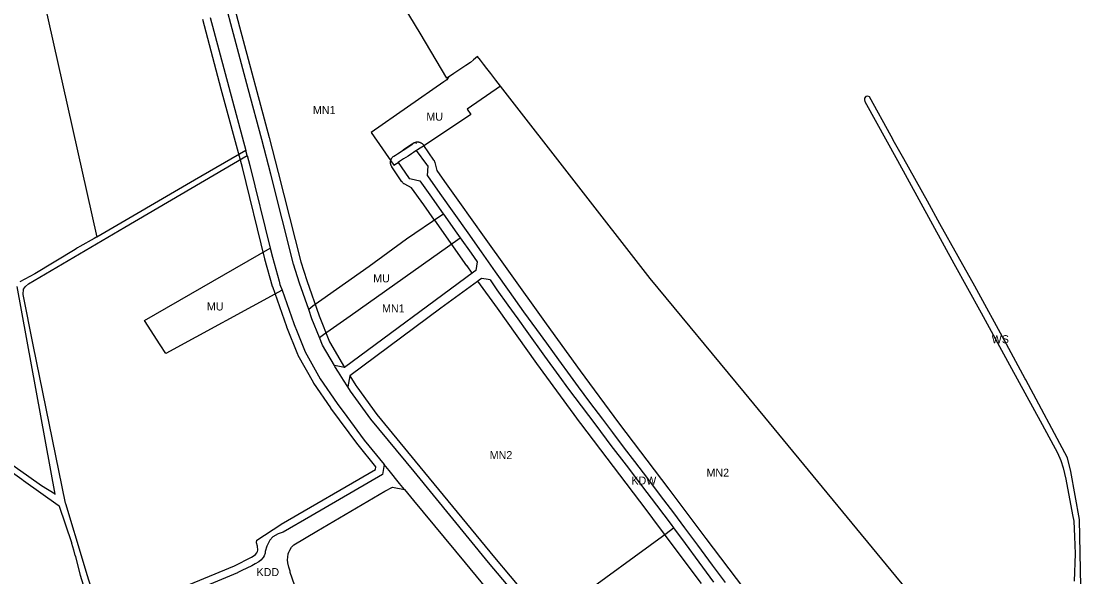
# Model space of a CAD drawing. Extents: x 7435758 to 7439981, y 5550649 to 5554049.
# Drawn here: x 7437107 to 7437796, y 5552004 to 5552365 of the extents above; entities that cross this region are included whole.
import ezdxf

# ---------------------------------------------------------------- set-up
doc = ezdxf.new("R2010")
doc.units = 0
for name, color, linetype in [('linie_rozgraniczające', 7, 'Continuous'), ('linie_zabudowy_nieprzekraczalne', 7, 'Continuous'), ('oznaczenia_przeznaczen', 7, 'Continuous')]:
    doc.layers.add(name, color=color, linetype=linetype)

msp = doc.modelspace()

# ---------------------------------------------------------------- linework, layer by layer
at = {"layer": 'linie_rozgraniczające'}
for p, q in [((7437079.69, 5552568.34), (7437156.51, 5552224.35)), ((7437366.62, 5552356.85), (7437322.07, 5552430.86)), ((7437244.46, 5552359.72), (7437240.84, 5552373.46)), ((7437230.33, 5552367.12), (7437242.26, 5552321.71)), ((7437254.97, 5552320.65), (7437244.46, 5552359.72)), ((7437384.15, 5552327.72), (7437366.62, 5552356.85)), ((7437399.4, 5552337.9), (7437396.39, 5552335.89)), ((7437401.44, 5552339.58), (7437399.4, 5552337.9)), ((7437404.02, 5552341.71), (7437401.44, 5552339.58)), ((7437405.85, 5552339.36), (7437404.02, 5552341.71)), ((7437407.81, 5552336.84), (7437405.85, 5552339.36)), ((7437396.39, 5552335.89), (7437388.59, 5552330.68)), ((7437410.14, 5552333.85), (7437407.81, 5552336.84)), ((7437412.64, 5552330.63), (7437410.14, 5552333.85)), ((7437382.18, 5552325.29), (7437334.96, 5552292.27)), ((7437384, 5552326.57), (7437382.18, 5552325.29)), ((7437385.04, 5552328.32), (7437384, 5552326.57)), ((7437385.04, 5552328.32), (7437384.15, 5552327.72)), ((7437388.59, 5552330.68), (7437385.04, 5552328.32)), ((7437415.98, 5552326.35), (7437412.64, 5552330.63)), ((7437418.98, 5552322.48), (7437415.98, 5552326.35)), ((7437242.26, 5552321.71), (7437253.38, 5552280.67)), ((7437263.81, 5552287.76), (7437254.97, 5552320.65)), ((7437418.98, 5552322.48), (7437397.35, 5552307.52)), ((7437516.1, 5552197.62), (7437418.98, 5552322.48)), ((7437655.54, 5552314.73), (7437655.41, 5552313.64)), ((7437655.41, 5552313.64), (7437655.82, 5552312.48)), ((7437656.32, 5552315.76), (7437655.54, 5552314.73)), ((7437655.82, 5552312.48), (7437676.89, 5552274.12)), ((7437657.66, 5552315.99), (7437656.32, 5552315.76)), ((7437658.85, 5552315.59), (7437657.66, 5552315.99)), ((7437672.77, 5552289.88), (7437658.85, 5552315.59)), ((7437399.69, 5552303.96), (7437369.51, 5552283.88)), ((7437397.35, 5552307.52), (7437399.69, 5552303.96)), ((7437334.96, 5552292.27), (7437349.56, 5552271.08)), ((7437675.01, 5552285.82), (7437672.77, 5552289.88)), ((7437269.61, 5552265.22), (7437263.81, 5552287.76)), ((7437369.44, 5552283.81), (7437365.01, 5552281.08)), ((7437369.51, 5552283.88), (7437369.44, 5552283.81)), ((7437681.11, 5552275.27), (7437675.01, 5552285.82)), ((7437174.82, 5552230.93), (7437254.27, 5552277.38)), ((7437253.34, 5552280.68), (7437220.13, 5552261.4)), ((7437253.38, 5552280.67), (7437253.34, 5552280.68)), ((7437254.27, 5552277.38), (7437253.38, 5552280.67)), ((7437254.27, 5552277.38), (7437256.04, 5552270.85)), ((7437358.84, 5552277.08), (7437355.98, 5552275.2)), ((7437360.99, 5552278.49), (7437358.84, 5552277.08)), ((7437362.29, 5552279.34), (7437360.99, 5552278.49)), ((7437362.39, 5552279.41), (7437362.29, 5552279.34)), ((7437363.85, 5552280.37), (7437362.39, 5552279.41)), ((7437364.34, 5552280.67), (7437363.85, 5552280.37)), ((7437363.85, 5552280.37), (7437363.85, 5552280.37)), ((7437365.01, 5552281.08), (7437364.34, 5552280.67)), ((7437371.06, 5552271.67), (7437364.34, 5552280.67)), ((7437256.04, 5552270.85), (7437269.23, 5552217.2)), ((7437349.56, 5552271.08), (7437351.43, 5552272.2)), ((7437351.43, 5552272.2), (7437352.43, 5552272.86)), ((7437352.45, 5552272.88), (7437352.43, 5552272.86)), ((7437352.43, 5552272.86), (7437359.11, 5552263.09)), ((7437353.35, 5552273.47), (7437352.45, 5552272.88)), ((7437355.98, 5552275.2), (7437353.35, 5552273.47)), ((7437371.79, 5552270.7), (7437371.06, 5552271.67)), ((7437371.52, 5552264.31), (7437371.81, 5552270.6)), ((7437371.82, 5552270.67), (7437371.79, 5552270.7)), ((7437371.81, 5552270.6), (7437371.82, 5552270.67)), ((7437676.89, 5552274.12), (7437713.49, 5552207.37)), ((7437696.41, 5552247.65), (7437681.11, 5552275.27)), ((7437284.35, 5552206.9), (7437269.61, 5552265.22)), ((7437359.11, 5552263.09), (7437359.48, 5552262.54)), ((7437359.48, 5552262.54), (7437360.8, 5552262.26)), ((7437360.8, 5552262.26), (7437366.56, 5552261.03)), ((7437371.66, 5552264.12), (7437371.52, 5552264.31)), ((7437379.76, 5552252.77), (7437371.66, 5552264.12)), ((7437220.13, 5552261.4), (7437156.51, 5552224.35)), ((7437366.56, 5552261.03), (7437373.02, 5552251.83)), ((7437373.02, 5552251.83), (7437381.76, 5552239.54)), ((7437388.85, 5552239.92), (7437379.76, 5552252.77)), ((7437704.46, 5552233.13), (7437696.41, 5552247.65)), ((7437380.2, 5552238.3), (7437357.78, 5552223.09)), ((7437380.21, 5552238.29), (7437380.2, 5552238.3)), ((7437381.85, 5552239.42), (7437380.21, 5552238.29)), ((7437381.76, 5552239.54), (7437381.85, 5552239.42)), ((7437381.85, 5552239.42), (7437390.59, 5552227.08)), ((7437397.86, 5552227.21), (7437388.85, 5552239.92)), ((7437112.18, 5552194.08), (7437174.82, 5552230.93)), ((7437716.46, 5552211.77), (7437704.46, 5552233.13)), ((7437154.93, 5552223.46), (7437145.61, 5552218.23)), ((7437156.01, 5552224.06), (7437154.93, 5552223.46)), ((7437156.51, 5552224.35), (7437156.01, 5552224.06)), ((7437321.15, 5552173.29), (7437391.19, 5552222.77)), ((7437357.78, 5552223.09), (7437333.62, 5552205.36)), ((7437390.59, 5552227.08), (7437392.81, 5552223.94)), ((7437391.18, 5552222.78), (7437392.81, 5552223.94)), ((7437391.19, 5552222.77), (7437391.18, 5552222.78)), ((7437392.81, 5552223.94), (7437399.86, 5552213.99)), ((7437406.64, 5552214.78), (7437397.86, 5552227.21)), ((7437142.42, 5552216.41), (7437116.22, 5552200.66)), ((7437143.39, 5552216.99), (7437142.42, 5552216.41)), ((7437144.04, 5552217.35), (7437143.39, 5552216.99)), ((7437145.61, 5552218.23), (7437144.04, 5552217.35)), ((7437187.49, 5552170.33), (7437269.23, 5552217.2)), ((7437269.23, 5552217.2), (7437270.66, 5552211.39)), ((7437399.86, 5552213.99), (7437403.84, 5552208.39)), ((7437415.77, 5552201.94), (7437406.64, 5552214.78)), ((7437270.66, 5552211.39), (7437275.01, 5552195.81)), ((7437288.27, 5552194.53), (7437284.35, 5552206.9)), ((7437403.84, 5552208.39), (7437403.39, 5552205.59)), ((7437713.49, 5552207.37), (7437731.24, 5552175.15)), ((7437727.15, 5552192.6), (7437716.46, 5552211.77)), ((7437116.22, 5552200.66), (7437106.53, 5552195.37)), ((7437333.62, 5552205.36), (7437297.06, 5552179.5)), ((7437401.33, 5552201.61), (7437317.61, 5552139.76)), ((7437402.94, 5552202.79), (7437401.33, 5552201.61)), ((7437403.39, 5552205.59), (7437402.94, 5552202.79)), ((7437424.78, 5552189.16), (7437415.77, 5552201.94)), ((7437110.17, 5552192.24), (7437112.18, 5552194.08)), ((7437275.01, 5552195.81), (7437275.61, 5552193.69)), ((7437275.61, 5552193.69), (7437276.92, 5552189.99)), ((7437294.3, 5552177.32), (7437288.27, 5552194.53)), ((7437403.96, 5552195.62), (7437380.16, 5552178.26)), ((7437405.11, 5552196.45), (7437403.96, 5552195.62)), ((7437406.64, 5552197.56), (7437405.11, 5552196.45)), ((7437409.57, 5552197.05), (7437406.64, 5552197.56)), ((7437412.16, 5552196.6), (7437409.57, 5552197.05)), ((7437412.16, 5552196.6), (7437416.63, 5552190.24)), ((7437577.43, 5552123.38), (7437516.1, 5552197.62)), ((7437104.48, 5552192.3), (7437129.36, 5552057.48)), ((7437108.62, 5552187.06), (7437108.96, 5552190.6)), ((7437115.07, 5552154.38), (7437108.62, 5552187.06)), ((7437108.96, 5552190.6), (7437110.17, 5552192.24)), ((7437276.92, 5552189.99), (7437201.36, 5552148.79)), ((7437276.92, 5552189.99), (7437284.61, 5552168.24)), ((7437416.63, 5552190.24), (7437423.78, 5552180.21)), ((7437434.2, 5552175.93), (7437424.78, 5552189.16)), ((7437747.82, 5552154.95), (7437727.15, 5552192.6)), ((7437297.06, 5552179.5), (7437294.3, 5552177.32)), ((7437423.78, 5552180.21), (7437430.1, 5552171.36)), ((7437296.36, 5552171.43), (7437294.3, 5552177.32)), ((7437303.97, 5552161.15), (7437321.15, 5552173.29)), ((7437380.16, 5552178.26), (7437320.93, 5552134.39)), ((7437442.45, 5552164.48), (7437434.2, 5552175.93)), ((7437731.24, 5552175.15), (7437749.69, 5552141.43)), ((7437197.73, 5552154.43), (7437187.49, 5552170.33)), ((7437284.61, 5552168.24), (7437284.8, 5552167.7)), ((7437284.8, 5552167.7), (7437286.68, 5552162.96)), ((7437301.2, 5552159.28), (7437296.36, 5552171.43)), ((7437430.1, 5552171.36), (7437436.07, 5552163.04)), ((7437286.68, 5552162.96), (7437291.87, 5552149.93)), ((7437301.2, 5552159.28), (7437303.97, 5552161.15)), ((7437303.25, 5552154.13), (7437301.2, 5552159.28)), ((7437436.07, 5552163.04), (7437447.53, 5552147.14)), ((7437448.98, 5552155.5), (7437442.45, 5552164.48)), ((7437136.22, 5552051.57), (7437115.07, 5552154.38)), ((7437201.36, 5552148.79), (7437197.73, 5552154.43)), ((7437310.95, 5552141.04), (7437303.25, 5552154.13)), ((7437456.77, 5552144.64), (7437448.98, 5552155.5)), ((7437760, 5552132.4), (7437747.82, 5552154.95)), ((7437291.87, 5552149.93), (7437301.69, 5552132.42)), ((7437447.53, 5552147.14), (7437456.84, 5552134.23)), ((7437311.29, 5552140.46), (7437310.95, 5552141.04)), ((7437317.61, 5552139.76), (7437310.95, 5552141.04)), ((7437313.58, 5552136.79), (7437311.29, 5552140.46)), ((7437464.33, 5552134.2), (7437456.77, 5552144.64)), ((7437749.69, 5552141.43), (7437770.97, 5552102.66)), ((7437301.69, 5552132.42), (7437312.76, 5552116.27)), ((7437316.93, 5552131.42), (7437313.58, 5552136.79)), ((7437319.6, 5552127.13), (7437316.93, 5552131.42)), ((7437320.93, 5552134.39), (7437319.6, 5552127.13)), ((7437456.84, 5552134.23), (7437463.18, 5552125.67)), ((7437469.54, 5552127.2), (7437464.33, 5552134.2)), ((7437760.4, 5552131.68), (7437760, 5552132.4)), ((7437787.5, 5552080.98), (7437760.4, 5552131.68)), ((7437321.38, 5552124.27), (7437319.6, 5552127.13)), ((7437334.65, 5552106.1), (7437321.38, 5552124.27)), ((7437463.18, 5552125.67), (7437471.29, 5552114.9)), ((7437477.04, 5552117.26), (7437469.54, 5552127.2)), ((7437712.83, 5551959.48), (7437577.43, 5552123.38)), ((7437312.76, 5552116.27), (7437318.98, 5552107.87)), ((7437471.29, 5552114.9), (7437480.87, 5552102.18)), ((7437485.41, 5552106.1), (7437477.04, 5552117.26)), ((7437318.98, 5552107.87), (7437330.32, 5552092.58)), ((7437362.72, 5552072.08), (7437334.65, 5552106.1)), ((7437491.86, 5552097.54), (7437485.41, 5552106.1)), ((7437480.87, 5552102.18), (7437490.64, 5552089.14)), ((7437499.63, 5552087.22), (7437491.86, 5552097.54)), ((7437770.97, 5552102.66), (7437781.02, 5552084.36)), ((7437330.32, 5552092.58), (7437343.33, 5552076.64)), ((7437490.64, 5552089.14), (7437500.52, 5552076.22)), ((7437506.29, 5552078.56), (7437499.63, 5552087.22)), ((7437781.02, 5552084.36), (7437783.21, 5552079.3)), ((7437087.82, 5552081.28), (7437107.84, 5552067.1)), ((7437112.44, 5552068.75), (7437099.88, 5552077.62)), ((7437343.33, 5552076.64), (7437342.16, 5552070.19)), ((7437346.52, 5552072.73), (7437343.33, 5552076.64)), ((7437500.52, 5552076.22), (7437510.48, 5552063.12)), ((7437514.63, 5552067.55), (7437506.29, 5552078.56)), ((7437783.21, 5552079.3), (7437784.67, 5552074.52)), ((7437789.65, 5552072.11), (7437787.5, 5552080.98)), ((7437342.16, 5552070.19), (7437295.7, 5552043.19)), ((7437353.33, 5552064.39), (7437346.52, 5552072.73)), ((7437411.17, 5552013.03), (7437362.72, 5552072.08)), ((7437784.67, 5552074.52), (7437786.41, 5552067.27)), ((7437795.23, 5552040.98), (7437789.65, 5552072.11)), ((7437107.84, 5552067.1), (7437108.81, 5552066.42)), ((7437108.81, 5552066.42), (7437131.4, 5552050.38)), ((7437120.68, 5552062.91), (7437112.44, 5552068.75)), ((7437129.38, 5552057.35), (7437120.68, 5552062.91)), ((7437356.55, 5552060.45), (7437353.33, 5552064.39)), ((7437510.48, 5552063.12), (7437520.24, 5552050.34)), ((7437522.95, 5552056.67), (7437514.63, 5552067.55)), ((7437786.41, 5552067.27), (7437790.79, 5552044.05)), ((7437129.36, 5552057.48), (7437129.38, 5552057.35)), ((7437299.49, 5552033.33), (7437343.69, 5552059.39)), ((7437343.69, 5552059.39), (7437348.84, 5552062.06)), ((7437348.84, 5552062.06), (7437356.55, 5552060.45)), ((7437356.55, 5552060.45), (7437362.34, 5552053.36)), ((7437531.55, 5552045.38), (7437522.95, 5552056.67)), ((7437131.4, 5552050.38), (7437132.1, 5552049.91)), ((7437132.1, 5552049.91), (7437132.17, 5552049.71)), ((7437132.17, 5552049.71), (7437140.08, 5552026.01)), ((7437136.35, 5552051.15), (7437136.22, 5552051.57)), ((7437147.89, 5552013.16), (7437136.35, 5552051.15)), ((7437362.34, 5552053.36), (7437395.89, 5552012.73)), ((7437520.24, 5552050.34), (7437529.75, 5552037.72)), ((7437295.7, 5552043.19), (7437277.58, 5552032.65)), ((7437538.83, 5552035.57), (7437531.55, 5552045.38)), ((7437790.79, 5552044.05), (7437791.58, 5552039.97)), ((7437526.54, 5552031.99), (7437531.36, 5552035.54)), ((7437529.75, 5552037.72), (7437531.36, 5552035.54)), ((7437531.36, 5552035.54), (7437538.85, 5552025.41)), ((7437547.22, 5552024.23), (7437538.83, 5552035.57)), ((7437791.58, 5552039.97), (7437791.99, 5552029.95)), ((7437796.11, 5551997.41), (7437795.23, 5552040.98)), ((7437270.9, 5552029.62), (7437268.91, 5552027.62)), ((7437274.5, 5552031.78), (7437270.9, 5552029.62)), ((7437276.3, 5552032.26), (7437274.5, 5552031.78)), ((7437277.58, 5552032.65), (7437276.3, 5552032.26)), ((7437284.61, 5552024.56), (7437299.49, 5552033.33)), ((7437465.45, 5551987.36), (7437526.53, 5552031.99)), ((7437526.53, 5552031.99), (7437526.54, 5552031.99)), ((7437791.99, 5552029.95), (7437792.45, 5552018.67)), ((7437140.08, 5552026.01), (7437140.19, 5552025.68)), ((7437140.19, 5552025.68), (7437141.37, 5552021.3)), ((7437141.37, 5552021.3), (7437142.34, 5552017.69)), ((7437267.07, 5552023.68), (7437266.07, 5552020.21)), ((7437268.91, 5552027.62), (7437267.07, 5552023.68)), ((7437281.43, 5552019.86), (7437282.01, 5552021.07)), ((7437282.01, 5552021.07), (7437283.12, 5552023.01)), ((7437283.12, 5552023.01), (7437284.61, 5552024.56)), ((7437538.85, 5552025.41), (7437547.91, 5552013.21)), ((7437551.91, 5552017.91), (7437547.22, 5552024.23)), ((7437142.34, 5552017.69), (7437142.38, 5552017.52)), ((7437142.38, 5552017.52), (7437145.78, 5552004.91)), ((7437263.22, 5552014.62), (7437261.76, 5552013.45)), ((7437264.65, 5552016.34), (7437263.22, 5552014.62)), ((7437265.32, 5552017.31), (7437264.65, 5552016.34)), ((7437266.04, 5552019.16), (7437265.32, 5552017.31)), ((7437266.07, 5552020.21), (7437266.04, 5552019.16)), ((7437280.53, 5552014.69), (7437280.61, 5552016.59)), ((7437280.69, 5552012.8), (7437280.53, 5552014.69)), ((7437280.61, 5552016.59), (7437280.93, 5552018.66)), ((7437280.93, 5552018.66), (7437281.43, 5552019.86)), ((7437556.73, 5552011.36), (7437551.91, 5552017.91)), ((7437792.45, 5552018.67), (7437791.72, 5552000.89)), ((7437150.34, 5552005.1), (7437147.89, 5552013.16)), ((7437250.76, 5552007.86), (7437248.29, 5552006.53)), ((7437257.28, 5552010.98), (7437250.76, 5552007.86)), ((7437259.45, 5552012.09), (7437257.28, 5552010.98)), ((7437261.76, 5552013.45), (7437259.45, 5552012.09)), ((7437281.35, 5552010.13), (7437280.69, 5552012.8)), ((7437282.18, 5552007.32), (7437281.35, 5552010.13)), ((7437282.21, 5552006.54), (7437282.18, 5552007.32)), ((7437395.89, 5552012.73), (7437419.08, 5551984.95)), ((7437438.35, 5551980.83), (7437411.17, 5552013.03)), ((7437547.91, 5552013.21), (7437557.39, 5552000.34)), ((7437565.08, 5552000.1), (7437556.73, 5552011.36)), ((7437145.78, 5552004.91), (7437151.85, 5551984.9)), ((7437152.86, 5551996.81), (7437150.34, 5552005.1)), ((7437247.92, 5552006.38), (7437206.29, 5551989.07)), ((7437248.29, 5552006.53), (7437247.92, 5552006.38)), ((7437288.06, 5551989.83), (7437282.21, 5552006.54))]:
    msp.add_line(p, q, dxfattribs=at)
at = {"layer": 'linie_zabudowy_nieprzekraczalne'}
for points in [[(7437120.71, 5552853.45), (7437125.86, 5552836.94), (7437125.94, 5552836.66), (7437131.09, 5552815.87), (7437153.26, 5552730.42), (7437165.89, 5552683.76), (7437165.92, 5552683.63), (7437165.93, 5552683.61), (7437177.48, 5552635.16), (7437206.88, 5552523.96), (7437206.89, 5552523.93), (7437225.25, 5552452.28), (7437249.29, 5552361.01), (7437268.64, 5552289.06), (7437268.66, 5552289.01), (7437274.45, 5552266.46), (7437274.46, 5552266.44), (7437289.16, 5552208.27), (7437293.01, 5552196.12), (7437301.05, 5552173.18), (7437307.75, 5552156.34), (7437317.61, 5552139.76)], [(7437177.37, 5551982.46), (7437245.97, 5552010.98), (7437257.04, 5552016.47), (7437258.92, 5552017.58), (7437259.7, 5552018.2), (7437260.66, 5552019.36), (7437261.08, 5552020.19), (7437261.11, 5552021.02), (7437260.93, 5552023.67), (7437260.26, 5552025.88), (7437260.28, 5552026.01), (7437260.51, 5552027.49), (7437276.09, 5552037.73), (7437276.44, 5552037.96), (7437337.69, 5552073.56), (7437338, 5552075.27), (7437326.45, 5552089.41), (7437326.3, 5552089.6), (7437308.74, 5552113.3), (7437308.72, 5552113.33), (7437308.63, 5552113.45), (7437297.56, 5552129.6), (7437297.46, 5552129.75), (7437297.33, 5552129.98), (7437287.5, 5552147.48), (7437287.47, 5552147.53), (7437287.33, 5552147.83), (7437287.22, 5552148.08), (7437280.15, 5552165.86), (7437280.13, 5552165.9), (7437280.08, 5552166.04), (7437270.89, 5552192.03), (7437270.83, 5552192.2), (7437270.79, 5552192.35), (7437265.84, 5552210.05), (7437265.8, 5552210.2), (7437251.2, 5552269.6), (7437237.43, 5552320.41), (7437237.42, 5552320.44), (7437225.49, 5552365.85)], [(7437576.99, 5551996.35), (7437552.66, 5552028.7), (7437552.66, 5552028.71), (7437528.54, 5552060.7), (7437528.53, 5552060.72), (7437495.79, 5552103.88), (7437470.94, 5552137.52), (7437448.78, 5552168.06), (7437423.25, 5552203.71), (7437408.49, 5552224.35), (7437392.56, 5552246.79), (7437382.85, 5552260.46), (7437377.7, 5552267.73), (7437376.41, 5552272.81), (7437376.34, 5552273.07), (7437376.23, 5552273.38), (7437376.1, 5552273.68), (7437375.96, 5552273.97), (7437375.79, 5552274.25), (7437375.68, 5552274.42), (7437369.13, 5552283.92), (7437369.05, 5552284.03), (7437368.85, 5552284.28), (7437368.63, 5552284.53), (7437368.4, 5552284.76), (7437368.15, 5552284.97), (7437367.89, 5552285.17), (7437367.62, 5552285.35), (7437367.33, 5552285.51), (7437367.04, 5552285.65), (7437366.73, 5552285.78), (7437366.42, 5552285.88), (7437366.11, 5552285.96), (7437365.79, 5552286.02), (7437365.46, 5552286.06), (7437365.13, 5552286.08), (7437364.81, 5552286.08), (7437364.48, 5552286.05), (7437364.16, 5552286.01), (7437363.84, 5552285.94), (7437363.52, 5552285.86), (7437363.21, 5552285.75), (7437362.91, 5552285.62), (7437362.62, 5552285.47), (7437362.39, 5552285.34), (7437361.23, 5552284.63), (7437361.18, 5552284.6), (7437361.11, 5552284.55), (7437355.63, 5552280.95), (7437361.94, 5552284.99)], [(7437363.9, 5552285.37), (7437363.98, 5552285.37), (7437364.3, 5552285.35), (7437364.34, 5552285.35), (7437364.18, 5552285.4), (7437363.9, 5552285.37)], [(7437400.53, 5552201.02), (7437397.18, 5552205.65), (7437397.15, 5552205.69), (7437376.17, 5552235.35), (7437376.13, 5552235.4), (7437369.05, 5552245.41), (7437369.05, 5552245.42), (7437361.08, 5552256.45), (7437356.68, 5552258.79), (7437356.42, 5552258.94), (7437356.15, 5552259.12), (7437355.89, 5552259.31), (7437355.64, 5552259.53), (7437355.41, 5552259.76), (7437355.19, 5552260), (7437354.99, 5552260.26), (7437354.89, 5552260.39), (7437348.31, 5552270.06), (7437348.22, 5552270.2), (7437348.06, 5552270.48), (7437347.91, 5552270.78), (7437347.78, 5552271.08), (7437347.67, 5552271.39), (7437347.59, 5552271.7), (7437347.52, 5552272.02), (7437347.48, 5552272.35), (7437347.45, 5552272.67), (7437347.45, 5552273), (7437347.47, 5552273.33), (7437347.51, 5552273.65), (7437347.57, 5552273.97), (7437347.65, 5552274.29), (7437347.75, 5552274.6), (7437347.88, 5552274.9), (7437348.02, 5552275.2), (7437348.18, 5552275.48), (7437348.36, 5552275.76), (7437348.56, 5552276.02), (7437348.77, 5552276.26), (7437349, 5552276.5), (7437349.25, 5552276.71), (7437349.5, 5552276.92), (7437349.7, 5552277.05), (7437350.6, 5552277.64), (7437351.95, 5552278.53), (7437355.63, 5552280.95)], [(7437549.63, 5551999.46), (7437526.05, 5552030.9), (7437526.04, 5552030.9), (7437525.79, 5552031.22), (7437522.21, 5552035.83), (7437513.69, 5552047.43), (7437471.05, 5552103.37), (7437470.99, 5552103.45), (7437442.61, 5552142.29), (7437442.61, 5552142.3), (7437442.58, 5552142.34), (7437416.92, 5552178.36), (7437404.27, 5552195.85)], [(7437320.93, 5552134.39), (7437324.87, 5552128.13), (7437325.53, 5552127.07), (7437338.6, 5552109.16), (7437366.58, 5552075.27), (7437366.59, 5552075.26), (7437415.01, 5552016.22), (7437445.57, 5551979.99)]]:
    msp.add_lwpolyline(points, dxfattribs=at)

# ---------------------------------------------------------------- texts
at = {"layer": 'oznaczenia_przeznaczen'}
for s, p in [('MN1', (7437297.01, 5552304.33)), ('MU', (7437370.74, 5552300.04)), ('MU', (7437336.16, 5552195.03)), ('MU', (7437228.1, 5552176.76)), ('MN1', (7437341.94, 5552175.5)), ('WS', (7437738.2, 5552155.5)), ('MN2', (7437411.92, 5552080.2)), ('MN2', (7437552.81, 5552068.79)), ('KDW', (7437503.99, 5552063.7)), ('KDD', (7437260.34, 5552004.22))]:
    msp.add_text(s, height=5.2, dxfattribs=at).set_placement(p)

doc.saveas('drawing.dxf')
